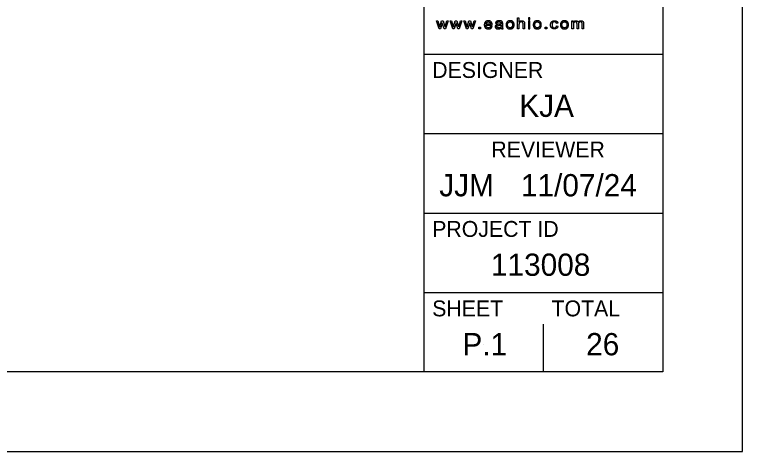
# Model space of a CAD drawing. Extents: x 0 to 40.9, y 0 to 22.
# Drawn here: x 29.425 to 34, y 0 to 2.749 of the extents above; entities that cross this region are included whole.
import ezdxf

# ---------------------------------------------------------------- set-up
doc = ezdxf.new("R2010")
doc.units = 0
for name, color, linetype in [('SH_Cut_Line', 7, 'Continuous'), ('SH_Data', 7, 'Continuous'), ('SH_Text', 7, 'Continuous'), ('TX_X_20', 7, 'Continuous')]:
    doc.layers.add(name, color=color, linetype=linetype)

msp = doc.modelspace()

# ---------------------------------------------------------------- linework, layer by layer
at = {"layer": 'SH_Cut_Line'}
for p, q in [((32.75, 0.5), (32.75, 0.8)), ((32.375, 0.675), (32.375, 0.675))]:
    msp.add_line(p, q, dxfattribs=at)
at = {"layer": 'SH_Data'}
msp.add_lwpolyline([(0, 0), (34, 0), (34, 22), (0, 22)], close=True, dxfattribs=at)
at = {"layer": 'SH_Text'}
for p, q in [((32, 0.5), (32, 21.5)), ((32, 2.5), (33.5, 2.5)), ((32, 2), (33.5, 2)), ((32, 1.5), (33.5, 1.5)), ((32, 1), (33.5, 1))]:
    msp.add_line(p, q, dxfattribs=at)
msp.add_lwpolyline([(1.5, 21.5), (33.5, 21.5), (33.5, 0.5), (1.5, 0.5)], close=True, dxfattribs=at)
at = {"layer": 'TX_X_20'}
for p, q in [((32.387, 2.6821), (32.4274, 2.6821)), ((32.4178, 2.6889), (32.3875, 2.6889)), ((32.4272, 2.6744), (32.4177, 2.6755)), ((32.4477, 2.6948), (32.4567, 2.6937)), ((32.4838, 2.6843), (32.4838, 2.6812)), ((32.4846, 2.6656), (32.4846, 2.6656)), ((32.4864, 2.6596), (32.496, 2.6596)), ((32.4931, 2.6802), (32.4931, 2.6913)), ((32.5143, 2.6842), (32.5143, 2.6842)), ((32.5238, 2.6842), (32.5238, 2.6842)), ((32.6852, 2.6842), (32.6852, 2.6842)), ((32.6946, 2.6842), (32.6946, 2.6842)), ((32.8402, 2.6944), (32.8313, 2.6931)), ((32.8321, 2.6776), (32.8411, 2.6765)), ((32.856, 2.6842), (32.856, 2.6842)), ((32.8655, 2.6842), (32.8655, 2.6842))]:
    msp.add_line(p, q, dxfattribs=at)
for points in [[(32.1007, 2.68), (32.1093, 2.7089), (32.1188, 2.7089), (32.1269, 2.6802), (32.1295, 2.6708), (32.1327, 2.6804), (32.142, 2.7089), (32.1509, 2.7089), (32.1339, 2.6596), (32.1244, 2.6596), (32.1158, 2.6891), (32.1137, 2.6975), (32.1027, 2.6596), (32.0931, 2.6596), (32.0766, 2.7089), (32.0861, 2.7089), (32.0947, 2.6804), (32.0979, 2.6698)], [(32.1867, 2.68), (32.1953, 2.7089), (32.2048, 2.7089), (32.2129, 2.6802), (32.2155, 2.6708), (32.2186, 2.6804), (32.228, 2.7089), (32.2369, 2.7089), (32.2199, 2.6596), (32.2104, 2.6596), (32.2018, 2.6891), (32.1997, 2.6975), (32.1886, 2.6596), (32.179, 2.6596), (32.1625, 2.7089), (32.172, 2.7089), (32.1807, 2.6804), (32.1838, 2.6698)], [(32.2726, 2.68), (32.2813, 2.7089), (32.2907, 2.7089), (32.2988, 2.6802), (32.3015, 2.6708), (32.3046, 2.6804), (32.3139, 2.7089), (32.3229, 2.7089), (32.3059, 2.6596), (32.2964, 2.6596), (32.2878, 2.6891), (32.2856, 2.6975), (32.2746, 2.6596), (32.265, 2.6596), (32.2485, 2.7089), (32.258, 2.7089), (32.2666, 2.6804), (32.2698, 2.6698)], [(32.5955, 2.6865), (32.5955, 2.6596), (32.5863, 2.6596), (32.5863, 2.7276), (32.5955, 2.7276), (32.5955, 2.7032)], [(32.9372, 2.6851), (32.9372, 2.6596), (32.928, 2.6596), (32.928, 2.7089), (32.9362, 2.7089), (32.9362, 2.7019)], [(32.6305, 2.6908), (32.6305, 2.6596), (32.6213, 2.6596), (32.6213, 2.6908)], [(32.9694, 2.6882), (32.9694, 2.6596), (32.9602, 2.6596), (32.9602, 2.6916)], [(33.0015, 2.6934), (33.0015, 2.6596), (32.9923, 2.6596), (32.9923, 2.6906)]]:
    msp.add_lwpolyline(points, dxfattribs=at)
for points in [[(32.655, 2.718), (32.6642, 2.718), (32.6642, 2.7276), (32.655, 2.7276)], [(32.655, 2.6596), (32.6642, 2.6596), (32.6642, 2.7089), (32.655, 2.7089)], [(32.3437, 2.6596), (32.3437, 2.669), (32.3541, 2.669), (32.3541, 2.6596)], [(32.7597, 2.6596), (32.7597, 2.669), (32.7702, 2.669), (32.7702, 2.6596)]]:
    msp.add_lwpolyline(points, close=True, dxfattribs=at)
for points in [[(32.3846, 2.7031), (32.3775, 2.6962), (32.3775, 2.6838)], [(32.4028, 2.71), (32.3916, 2.71), (32.3846, 2.7031)], [(32.3923, 2.6992), (32.3966, 2.7031), (32.4029, 2.7031)], [(32.4206, 2.7032), (32.4137, 2.71), (32.4028, 2.71)], [(32.4029, 2.7031), (32.4099, 2.7031), (32.4143, 2.6983)], [(32.4275, 2.6843), (32.4275, 2.6965), (32.4206, 2.7032)], [(32.4517, 2.7032), (32.4489, 2.7), (32.4477, 2.6948)], [(32.4598, 2.7082), (32.4545, 2.7065), (32.4517, 2.7032)], [(32.4567, 2.6937), (32.4581, 2.6989), (32.4612, 2.701)], [(32.4721, 2.71), (32.4651, 2.71), (32.4598, 2.7082)], [(32.4612, 2.701), (32.4643, 2.7031), (32.4708, 2.7031)], [(32.4708, 2.7031), (32.4777, 2.7031), (32.4812, 2.7002)], [(32.4834, 2.7085), (32.479, 2.71), (32.4721, 2.71)], [(32.4812, 2.7002), (32.4838, 2.6981), (32.4838, 2.693)], [(32.4897, 2.7047), (32.4877, 2.707), (32.4834, 2.7085)], [(32.4926, 2.699), (32.4918, 2.7025), (32.4897, 2.7047)], [(32.5227, 2.7045), (32.5143, 2.6979), (32.5143, 2.6842)], [(32.5398, 2.71), (32.5297, 2.71), (32.5227, 2.7045)], [(32.5283, 2.6984), (32.5329, 2.7031), (32.5398, 2.7031)], [(32.558, 2.7033), (32.5509, 2.71), (32.5398, 2.71)], [(32.5398, 2.7031), (32.5465, 2.7031), (32.5511, 2.6983)], [(32.5651, 2.6849), (32.5651, 2.6966), (32.558, 2.7033)], [(32.5955, 2.7032), (32.602, 2.71), (32.6118, 2.71)], [(32.6022, 2.7008), (32.5986, 2.6989), (32.5971, 2.6956)], [(32.6099, 2.7028), (32.6058, 2.7028), (32.6022, 2.7008)], [(32.6183, 2.6999), (32.6153, 2.7028), (32.6099, 2.7028)], [(32.6118, 2.71), (32.6178, 2.71), (32.6222, 2.7078)], [(32.6213, 2.6908), (32.6213, 2.697), (32.6183, 2.6999)], [(32.6222, 2.7078), (32.6267, 2.7056), (32.6286, 2.7018)], [(32.6286, 2.7018), (32.6305, 2.698), (32.6305, 2.6908)], [(32.6935, 2.7045), (32.6852, 2.6979), (32.6852, 2.6842)], [(32.7106, 2.71), (32.7005, 2.71), (32.6935, 2.7045)], [(32.6992, 2.6984), (32.7037, 2.7031), (32.7106, 2.7031)], [(32.7288, 2.7033), (32.7218, 2.71), (32.7106, 2.71)], [(32.7106, 2.7031), (32.7174, 2.7031), (32.7219, 2.6983)], [(32.7359, 2.6849), (32.7359, 2.6966), (32.7288, 2.7033)], [(32.7968, 2.698), (32.7997, 2.704), (32.8056, 2.707)], [(32.8056, 2.707), (32.8116, 2.71), (32.8186, 2.71)], [(32.8189, 2.7031), (32.812, 2.7031), (32.8077, 2.6986)], [(32.8186, 2.71), (32.8274, 2.71), (32.833, 2.7059)], [(32.8268, 2.7006), (32.8235, 2.7031), (32.8189, 2.7031)], [(32.8313, 2.6931), (32.83, 2.6981), (32.8268, 2.7006)], [(32.833, 2.7059), (32.8387, 2.7018), (32.8402, 2.6944)], [(32.8644, 2.7045), (32.856, 2.6979), (32.856, 2.6842)], [(32.8814, 2.71), (32.8714, 2.71), (32.8644, 2.7045)], [(32.87, 2.6984), (32.8745, 2.7031), (32.8814, 2.7031)], [(32.8997, 2.7033), (32.8926, 2.71), (32.8814, 2.71)], [(32.8814, 2.7031), (32.8882, 2.7031), (32.8927, 2.6983)], [(32.9068, 2.6849), (32.9068, 2.6966), (32.8997, 2.7033)], [(32.9362, 2.7019), (32.9388, 2.7055), (32.943, 2.7077)], [(32.9434, 2.7008), (32.9401, 2.699), (32.9387, 2.6954)], [(32.943, 2.7077), (32.9472, 2.71), (32.9527, 2.71)], [(32.9506, 2.7027), (32.9467, 2.7027), (32.9434, 2.7008)], [(32.958, 2.6999), (32.9557, 2.7027), (32.9506, 2.7027)], [(32.9527, 2.71), (32.9587, 2.71), (32.9625, 2.7077)], [(32.9602, 2.6916), (32.9602, 2.6971), (32.958, 2.6999)], [(32.9625, 2.7077), (32.9664, 2.7054), (32.968, 2.7013)], [(32.968, 2.7013), (32.9744, 2.71), (32.9847, 2.71)], [(32.9827, 2.7027), (32.977, 2.7027), (32.9732, 2.6992)], [(32.9882, 2.7014), (32.9858, 2.7027), (32.9827, 2.7027)], [(32.9847, 2.71), (32.9928, 2.71), (32.9972, 2.7059)], [(32.9914, 2.6978), (32.9905, 2.7), (32.9882, 2.7014)], [(32.9972, 2.7059), (33.0015, 2.7018), (33.0015, 2.6934)], [(32.0979, 2.6698), (32.0981, 2.6706), (32.1007, 2.68)], [(32.1838, 2.6698), (32.184, 2.6706), (32.1867, 2.68)], [(32.2698, 2.6698), (32.27, 2.6706), (32.2726, 2.68)], [(32.3775, 2.6838), (32.3775, 2.6718), (32.3845, 2.6651)], [(32.3845, 2.6651), (32.3915, 2.6585), (32.4034, 2.6585)], [(32.3921, 2.6696), (32.3875, 2.6739), (32.387, 2.6821)], [(32.3875, 2.6889), (32.388, 2.6954), (32.3923, 2.6992)], [(32.4034, 2.6653), (32.3966, 2.6653), (32.3921, 2.6696)], [(32.412, 2.6677), (32.4085, 2.6653), (32.4034, 2.6653)], [(32.4034, 2.6585), (32.4128, 2.6585), (32.4189, 2.6626)], [(32.4177, 2.6755), (32.4156, 2.6702), (32.412, 2.6677)], [(32.4143, 2.6983), (32.4172, 2.6951), (32.4178, 2.6889)], [(32.4189, 2.6626), (32.4249, 2.6668), (32.4272, 2.6744)], [(32.4274, 2.6821), (32.4275, 2.6835), (32.4275, 2.6843)], [(32.4479, 2.6792), (32.4461, 2.6762), (32.4461, 2.6726)], [(32.4461, 2.6726), (32.4461, 2.6664), (32.4509, 2.6624)], [(32.4526, 2.684), (32.4497, 2.6822), (32.4479, 2.6792)], [(32.4509, 2.6624), (32.4556, 2.6585), (32.4646, 2.6585)], [(32.4592, 2.6867), (32.4555, 2.6858), (32.4526, 2.684)], [(32.4559, 2.6728), (32.4559, 2.675), (32.4571, 2.6768)], [(32.4586, 2.6672), (32.4559, 2.6695), (32.4559, 2.6728)], [(32.4571, 2.6768), (32.4584, 2.6785), (32.4608, 2.6795)], [(32.4668, 2.665), (32.4614, 2.665), (32.4586, 2.6672)], [(32.4674, 2.688), (32.4619, 2.6873), (32.4592, 2.6867)], [(32.4608, 2.6795), (32.4631, 2.6804), (32.4688, 2.6811)], [(32.4646, 2.6585), (32.47, 2.6585), (32.4747, 2.6601)], [(32.4762, 2.6671), (32.4721, 2.665), (32.4668, 2.665)], [(32.4838, 2.6908), (32.4785, 2.6892), (32.4674, 2.688)], [(32.4688, 2.6811), (32.4788, 2.6824), (32.4838, 2.6843)], [(32.4747, 2.6601), (32.4794, 2.6617), (32.4846, 2.6656)], [(32.4823, 2.6729), (32.4803, 2.6692), (32.4762, 2.6671)], [(32.4838, 2.6812), (32.4838, 2.6757), (32.4823, 2.6729)], [(32.4838, 2.693), (32.4838, 2.6925), (32.4838, 2.6908)], [(32.4846, 2.6656), (32.485, 2.6622), (32.4864, 2.6596)], [(32.4931, 2.6913), (32.4931, 2.6969), (32.4926, 2.699)], [(32.4936, 2.6655), (32.4931, 2.6686), (32.4931, 2.6802)], [(32.496, 2.6596), (32.4942, 2.6624), (32.4936, 2.6655)], [(32.5143, 2.6842), (32.5143, 2.6717), (32.5214, 2.6651)], [(32.5214, 2.6651), (32.5284, 2.6585), (32.5398, 2.6585)], [(32.5238, 2.6842), (32.5238, 2.6937), (32.5283, 2.6984)], [(32.5283, 2.67), (32.5238, 2.6747), (32.5238, 2.6842)], [(32.5398, 2.6653), (32.5329, 2.6653), (32.5283, 2.67)], [(32.5511, 2.6701), (32.5466, 2.6653), (32.5398, 2.6653)], [(32.5398, 2.6585), (32.5468, 2.6585), (32.5528, 2.6615)], [(32.5511, 2.6983), (32.5556, 2.6936), (32.5556, 2.6845)], [(32.5556, 2.6845), (32.5556, 2.6748), (32.5511, 2.6701)], [(32.5528, 2.6615), (32.5588, 2.6645), (32.562, 2.67)], [(32.562, 2.67), (32.5651, 2.6754), (32.5651, 2.6849)], [(32.5971, 2.6956), (32.5955, 2.6923), (32.5955, 2.6865)], [(32.6852, 2.6842), (32.6852, 2.6717), (32.6922, 2.6651)], [(32.6922, 2.6651), (32.6992, 2.6585), (32.7106, 2.6585)], [(32.6946, 2.6842), (32.6946, 2.6937), (32.6992, 2.6984)], [(32.6992, 2.67), (32.6946, 2.6747), (32.6946, 2.6842)], [(32.7106, 2.6653), (32.7037, 2.6653), (32.6992, 2.67)], [(32.7219, 2.6701), (32.7174, 2.6653), (32.7106, 2.6653)], [(32.7106, 2.6585), (32.7177, 2.6585), (32.7237, 2.6615)], [(32.7219, 2.6983), (32.7265, 2.6936), (32.7265, 2.6845)], [(32.7265, 2.6845), (32.7265, 2.6748), (32.7219, 2.6701)], [(32.7237, 2.6615), (32.7297, 2.6645), (32.7328, 2.67)], [(32.7328, 2.67), (32.7359, 2.6754), (32.7359, 2.6849)], [(32.7939, 2.684), (32.7939, 2.692), (32.7968, 2.698)], [(32.8006, 2.6651), (32.7939, 2.6717), (32.7939, 2.684)], [(32.8185, 2.6585), (32.8074, 2.6585), (32.8006, 2.6651)], [(32.8077, 2.6986), (32.8033, 2.6941), (32.8033, 2.6843)], [(32.8033, 2.6843), (32.8033, 2.6743), (32.8075, 2.6698)], [(32.8075, 2.6698), (32.8117, 2.6653), (32.8185, 2.6653)], [(32.8185, 2.6653), (32.8239, 2.6653), (32.8275, 2.6683)], [(32.8335, 2.6633), (32.8274, 2.6585), (32.8185, 2.6585)], [(32.8275, 2.6683), (32.8311, 2.6713), (32.8321, 2.6776)], [(32.8411, 2.6765), (32.8396, 2.668), (32.8335, 2.6633)], [(32.856, 2.6842), (32.856, 2.6717), (32.863, 2.6651)], [(32.863, 2.6651), (32.87, 2.6585), (32.8814, 2.6585)], [(32.8655, 2.6842), (32.8655, 2.6937), (32.87, 2.6984)], [(32.87, 2.67), (32.8655, 2.6747), (32.8655, 2.6842)], [(32.8814, 2.6653), (32.8745, 2.6653), (32.87, 2.67)], [(32.8928, 2.6701), (32.8882, 2.6653), (32.8814, 2.6653)], [(32.8814, 2.6585), (32.8885, 2.6585), (32.8945, 2.6615)], [(32.8927, 2.6983), (32.8973, 2.6936), (32.8973, 2.6845)], [(32.8973, 2.6845), (32.8973, 2.6748), (32.8928, 2.6701)], [(32.8945, 2.6615), (32.9005, 2.6645), (32.9036, 2.67)], [(32.9036, 2.67), (32.9068, 2.6754), (32.9068, 2.6849)], [(32.9387, 2.6954), (32.9372, 2.6918), (32.9372, 2.6851)], [(32.9732, 2.6992), (32.9694, 2.6958), (32.9694, 2.6882)], [(32.9923, 2.6906), (32.9923, 2.6956), (32.9914, 2.6978)]]:
    msp.add_open_spline(points, degree=2, dxfattribs=at)

# ---------------------------------------------------------------- texts
at = {"layer": 'SH_Cut_Line'}
for s, height, p in [('DESIGNER', 0.1, (32.05, 2.35)), ('KJA', 0.14, (32.5975, 2.105)), ('REVIEWER', 0.1, (32.4218, 1.85)), ('JJM', 0.14, (32.0946, 1.605)), ('11/07/24', 0.14, (32.6078, 1.605)), ('PROJECT ID', 0.1, (32.05, 1.35)), ('113008', 0.14, (32.4193, 1.105)), ('SHEET', 0.1, (32.05, 0.85)), ('TOTAL', 0.1, (32.8, 0.85)), ('P.1', 0.14, (32.2403, 0.605)), ('26', 0.14, (33.0176, 0.605))]:
    msp.add_text(s, height=height, dxfattribs=at).set_placement(p)

doc.saveas('drawing.dxf')
